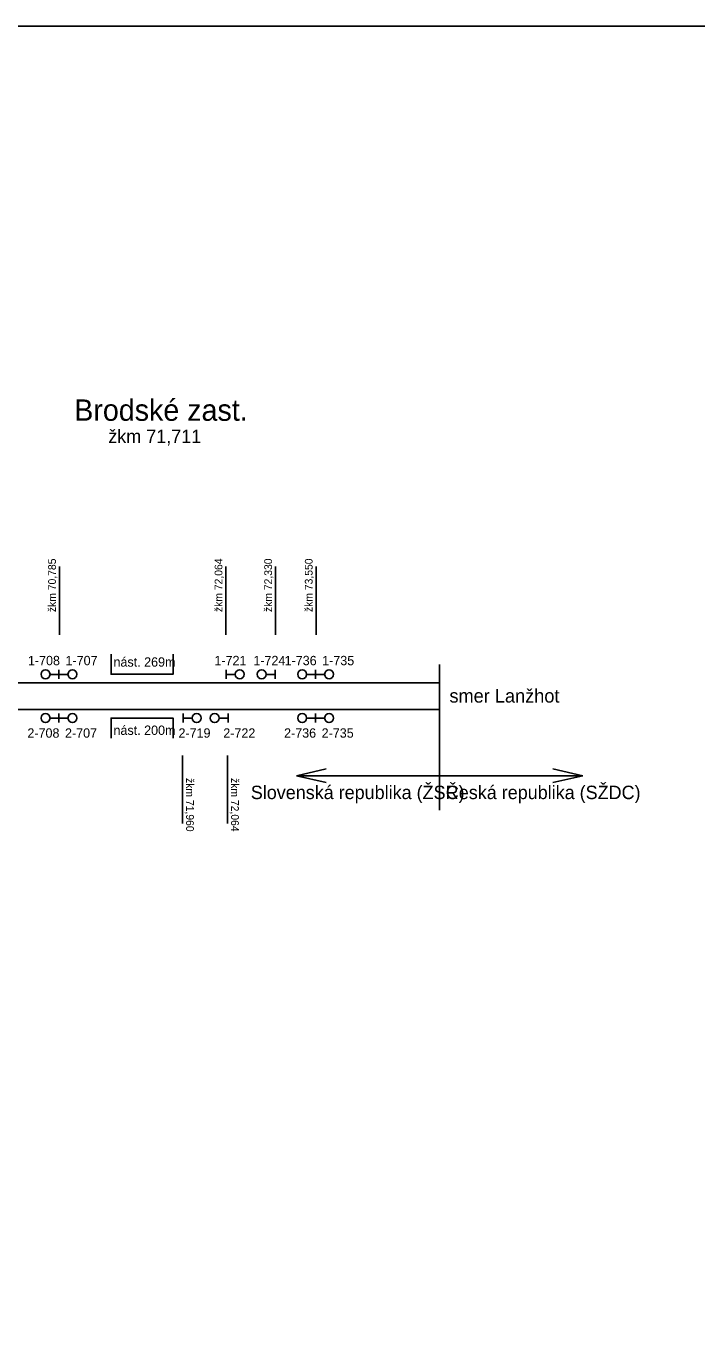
# Model space of a CAD drawing. Extents: x -119 to 851, y -238 to 59.
# Drawn here: x 598.1 to 648.2, y -38.4 to 59 of the extents above; entities that cross this region are included whole.
import ezdxf

# ---------------------------------------------------------------- set-up
doc = ezdxf.new("R2010")
doc.units = 0
for name, color, linetype in [('Default', 7, 'Continuous'), ('nastupistia', 7, 'Continuous'), ('netlač', 7, 'Continuous'), ('popisky navestidla', 7, 'Continuous'), ('popisky stanic a zastavok', 7, 'Continuous'), ('PU_navestidla', 7, 'Continuous'), ('PU_oznacenie navestidiel', 7, 'Continuous'), ('PU_vlecky', 7, 'Continuous'), ('statna hranica', 7, 'Continuous')]:
    doc.layers.add(name, color=color, linetype=linetype)

msp = doc.modelspace()

# ---------------------------------------------------------------- linework, layer by layer
at = {"layer": 'Default'}
for p, q in [((618.311, 2.94), (620.53, 3.448)), ((629.005, 2.94), (618.311, 2.94)), ((618.311, 2.94), (620.53, 2.432)), ((629.005, 2.94), (639.699, 2.94)), ((639.699, 2.94), (637.48, 3.448)), ((639.699, 2.94), (637.48, 2.432))]:
    msp.add_line(p, q, dxfattribs=at)
at = {"layer": 'nastupistia'}
for points in [[(609.087, 12.027), (609.087, 10.523), (604.45, 10.523), (604.45, 12.027)], [(609.088, 5.75), (609.088, 7.254), (604.45, 7.254), (604.45, 5.75)]]:
    msp.add_lwpolyline(points, dxfattribs=at)
at = {"layer": 'netlač'}
for p, q in [((591.856, 9.889), (629.005, 9.889)), ((591.856, 7.89), (629.005, 7.89))]:
    msp.add_line(p, q, dxfattribs=at)
at = {"layer": 'popisky navestidla'}
for p, q in [((600.595, 13.488), (600.595, 18.579)), ((613.036, 13.488), (613.036, 18.579)), ((616.745, 13.488), (616.745, 18.579)), ((619.777, 13.488), (619.777, 18.579)), ((609.799, 4.46), (609.799, -0.631)), ((613.16, 4.46), (613.16, -0.631))]:
    msp.add_line(p, q, dxfattribs=at)
msp.add_lwpolyline([(-118.951, -238.008), (851.049, -238.008), (851.049, 58.992), (-118.951, 58.992)], close=True, dxfattribs=at)
at = {"layer": 'PU_navestidla'}
for p, q in [((600.562, 10.86), (600.562, 10.188)), ((600.562, 10.86), (600.562, 10.188)), ((613.066, 10.86), (613.066, 10.188)), ((616.712, 10.86), (616.712, 10.188)), ((619.743, 10.86), (619.743, 10.188)), ((619.743, 10.86), (619.743, 10.188)), ((600.562, 10.522), (599.89, 10.522)), ((600.562, 10.522), (601.234, 10.522)), ((613.066, 10.522), (613.738, 10.522)), ((616.712, 10.522), (616.04, 10.522)), ((619.743, 10.522), (619.071, 10.522)), ((619.743, 10.522), (620.415, 10.522)), ((600.562, 7.254), (599.89, 7.254)), ((600.562, 6.917), (600.562, 7.589)), ((600.562, 6.917), (600.562, 7.589)), ((600.562, 7.254), (601.234, 7.254)), ((609.838, 6.917), (609.838, 7.589)), ((609.838, 7.254), (610.51, 7.254)), ((613.199, 7.254), (612.527, 7.254)), ((613.199, 6.917), (613.199, 7.589)), ((619.743, 7.254), (619.071, 7.254)), ((619.743, 6.917), (619.743, 7.589)), ((619.743, 6.917), (619.743, 7.589)), ((619.743, 7.254), (620.415, 7.254))]:
    msp.add_line(p, q, dxfattribs=at)
for centre in [(599.554, 10.524), (601.57, 10.524), (614.074, 10.524), (615.704, 10.524), (618.735, 10.524), (620.751, 10.524), (599.554, 7.253), (601.57, 7.253), (610.846, 7.253), (612.191, 7.253), (618.735, 7.253), (620.751, 7.253)]:
    msp.add_circle(centre, 0.336, dxfattribs=at)
at = {"layer": 'statna hranica'}
msp.add_line((629.005, 11.25), (629.005, 0.37), dxfattribs=at)

# ---------------------------------------------------------------- texts
at = {"layer": 'Default'}
for s, p in [('Slovenská republika (ŽSR)', (614.894, 1.193)), ('Česká republika (SŽDC)', (629.469, 1.193))]:
    msp.add_text(s, height=1.00438, dxfattribs=at).set_placement(p)
at = {"layer": 'nastupistia'}
for s, p in [('nást. 269m', (604.635, 11.096)), ('nást. 200m', (604.635, 5.993))]:
    msp.add_text(s, height=0.7, dxfattribs=at).set_placement(p)
at = {"layer": 'popisky navestidla'}
for s, rotation, p in [('žkm 70,785', 90, (600.332, 15.175)), ('žkm 72,064', 90, (612.773, 15.18)), ('žkm 72,330', 90, (616.482, 15.18)), ('žkm 73,550', 90, (619.514, 15.18)), ('žkm 71,960', 270, (610.062, 2.768)), ('žkm 72,064', 270, (613.423, 2.768))]:
    msp.add_text(s, height=0.5793, rotation=rotation, dxfattribs=at).set_placement(p)
at = {"layer": 'popisky stanic a zastavok'}
for s, height, p in [('Brodské zast.', 1.6, (601.702, 29.479)), ('žkm 71,711', 1.0044, (604.245, 27.811))]:
    msp.add_text(s, height=height, dxfattribs=at).set_placement(p)
at = {"layer": 'PU_oznacenie navestidiel'}
for s, p in [('1-708', (598.239, 11.203)), ('1-707', (601.05, 11.203)), ('1-721', (612.176, 11.203)), ('1-724', (615.087, 11.203)), ('1-736', (617.422, 11.203)), ('1-735', (620.23, 11.203)), ('2-708', (598.201, 5.786)), ('2-707', (601.012, 5.786)), ('2-719', (609.49, 5.786)), ('2-722', (612.84, 5.786)), ('2-736', (617.383, 5.786)), ('2-735', (620.191, 5.786))]:
    msp.add_text(s, height=0.7, dxfattribs=at).set_placement(p)
at = {"layer": 'PU_vlecky'}
msp.add_text('smer Lanžhot', height=1.015, dxfattribs=at).set_placement((629.741, 8.408))

doc.saveas('drawing.dxf')
